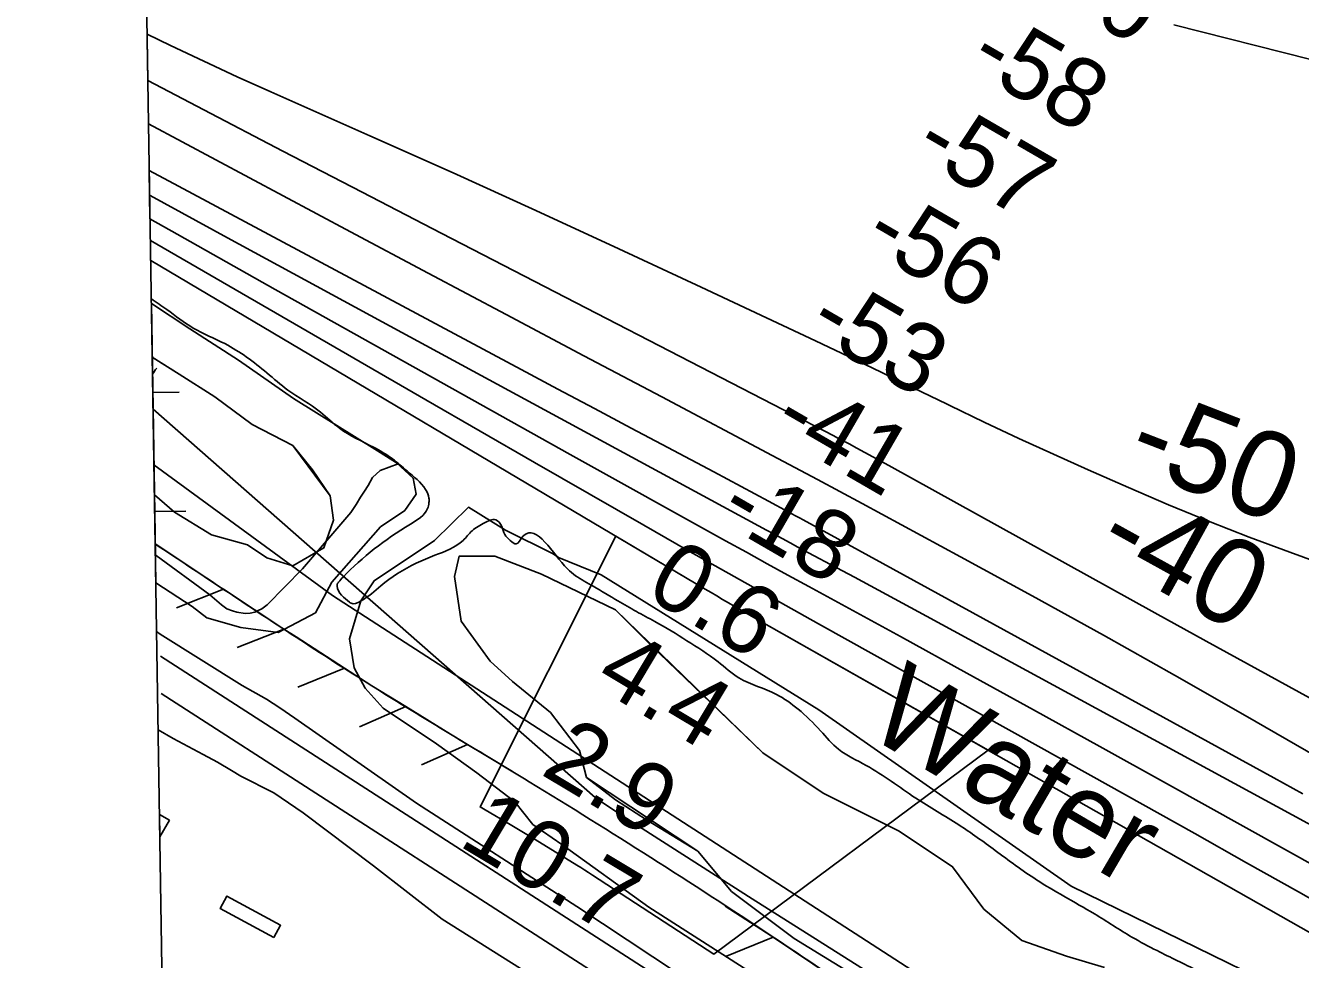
# Model space of a CAD drawing. Extents: x 3855477 to 3893699, y 299188 to 325115.
# Drawn here: x 3859445 to 3860680, y 314472 to 315377 of the extents above; entities that cross this region are included whole.
import ezdxf

# ---------------------------------------------------------------- set-up
doc = ezdxf.new("R2010")
doc.units = 0
for name, color, linetype in [('V-BLDG-OTLN', 7, 'Continuous'), ('V-GRID-FRAM', 7, 'Continuous'), ('V-LEVE-TOET', 7, 'Continuous'), ('V-RIVR-EDGE', 7, 'Continuous'), ('V-RIVR-IDEN', 7, 'Continuous'), ('V-RIVR-RANG', 7, 'Continuous'), ('V-RRAP-FSHR', 7, 'Continuous'), ('V-SITE-VEGE', 7, 'Continuous'), ('V-SURV-LINE', 7, 'Continuous'), ('V-TOPO-DPTH', 7, 'Continuous'), ('V-TOPO-MAJR', 7, 'Continuous'), ('V-TOPO-MAJR-IDEN', 7, 'Continuous'), ('V-TOPO-MINR', 7, 'Continuous'), ('V-TOPO-MINR-IDEN', 7, 'Continuous'), ('V-TOPO-SHOR', 7, 'Continuous'), ('V-TOPO-WATR', 7, 'Continuous'), ('V-WETL-SWMP', 7, 'Continuous')]:
    doc.layers.add(name, color=color, linetype=linetype)

msp = doc.modelspace()

# ---------------------------------------------------------------- linework, layer by layer
at = {"layer": 'V-BLDG-OTLN'}
for p, q in [((3859575.4, 314591.1), (3859575.1, 314612.7)), ((3859575.1, 314612.7), (3859584.7, 314607.2)), ((3859584.7, 314607.2), (3859575.4, 314591.1))]:
    msp.add_line(p, q, dxfattribs=at)
msp.add_lwpolyline([(3859685.8, 314493.4), (3859633.9, 314521.6), (3859640.4, 314533.6), (3859692.3, 314505.4)], close=True, dxfattribs=at)
at = {"layer": 'V-GRID-FRAM'}
msp.add_lwpolyline([(3859445.3, 322797), (3891292.6, 323315.8), (3891596.8, 305135.9), (3859733.6, 304616.8), (3859445.3, 322797)], dxfattribs=at)
at = {"layer": 'V-LEVE-TOET'}
for points in [[(3862242.2, 313100.5), (3862093.7, 313191.4), (3861941.9, 313285.1), (3861815.6, 313363.6), (3861686.6, 313438.4), (3861563.5, 313515.7), (3861444.2, 313584.7), (3861308.7, 313671.1), (3861176.5, 313754.8), (3861033.5, 313846.5), (3860865.7, 313952.6), (3860666.5, 314081.9), (3860455.2, 314218.1), (3860280.2, 314328.3), (3860126.5, 314425.9), (3859979.2, 314523.5), (3859824, 314623.6), (3859706.2, 314705.8), (3859691.7, 314716.1), (3859678.8, 314724.5), (3859655.1, 314737.6), (3859575.8, 314787.4), (3859572.3, 314789.8)], [(3859573.8, 314694.8), (3859588.3, 314686.4), (3859617.3, 314670.8), (3859631.3, 314663.3), (3859644.8, 314655.3), (3859654, 314649.7), (3859685.8, 314633.6), (3859714.4, 314614.3), (3859782.2, 314562.9), (3859848.9, 314511.4), (3859933.3, 314457.9), (3859995.9, 314420.4), (3860084.2, 314363.8), (3860165, 314312), (3860251.4, 314257.3), (3860353.4, 314191.6), (3860436.3, 314134.5), (3860515.4, 314085.3), (3860590.9, 314036.6), (3860660.7, 313988.8), (3860749.4, 313935.7)]]:
    msp.add_lwpolyline(points, dxfattribs=at)
at = {"layer": 'V-RIVR-EDGE'}
msp.add_spline([(3859567.2, 315112.1), (3859582.1, 315101.8), (3859607.8, 315083.8), (3859638.4, 315068.7), (3859679.1, 315040.4), (3859699.4, 315023.8), (3859731, 315002.4), (3859749.4, 314986.8), (3859782.4, 314968.3), (3859800.8, 314957.1), (3859814.8, 314945.4), (3859832.8, 314927.4), (3859836.1, 314919.1), (3859836.1, 314914.7), (3859834.7, 314908.9), (3859818.1, 314893.9), (3859752.9, 314842.6), (3859748.5, 314837.7), (3859747.1, 314835.3), (3859747.1, 314833.8), (3859759.2, 314818.3), (3859760.6, 314817.3), (3859769.8, 314819.2), (3859789.3, 314834.2), (3859823.8, 314856), (3859841.8, 314863.7), (3859869.1, 314878.2), (3859877.8, 314887.4), (3859890, 314895.2), (3859895.3, 314897.6), (3859900.7, 314898.1), (3859906.5, 314891.7), (3859909.4, 314883.9), (3859914.7, 314878.1), (3859920.5, 314874.7), (3859926.9, 314882), (3859927.8, 314882.9), (3859970, 314850.8), (3859986.5, 314838.6), (3859995.2, 314833.7), (3860019, 314819.6), (3860036.9, 314809.3), (3860054.9, 314799.6), (3860085.9, 314781), (3860116, 314760.6), (3860136.3, 314745), (3860172.7, 314728.9), (3860193.5, 314714.7), (3860215.3, 314693.8), (3860232.8, 314675.8), (3860259.5, 314660.2), (3860307.5, 314628.5), (3860349.2, 314602.6), (3860384.5, 314577.8), (3860424.3, 314549.5), (3860451, 314533.4), (3860480.5, 314516.4), (3860516.9, 314493.9), (3860541.2, 314480.8), (3860580.5, 314461.2), (3860606.2, 314447.1), (3860637.2, 314429.5), (3860661.4, 314415.4), (3860700.7, 314395.4), (3860743.4, 314370), (3860763.8, 314358.3), (3860794.3, 314340.3), (3860827.8, 314322.7), (3860852.5, 314307.6), (3860870.5, 314295.4), (3860907.3, 314274.4), (3860941.3, 314254), (3860954.8, 314253), (3860974.2, 314243.2), (3861007.7, 314223.7), (3861035.3, 314204.7), (3861088.7, 314172), (3861147.4, 314134.5), (3861171.6, 314117.4), (3861230.3, 314081.8)], degree=3, dxfattribs=at)
at = {"layer": 'V-RRAP-FSHR'}
for p, q in [((3859637.1, 314830.8), (3859591.7, 314812.9)), ((3859695.6, 314792.3), (3859650.3, 314774.3)), ((3859754.4, 314754.3), (3859709.2, 314735.9)), ((3859813.7, 314717.1), (3859768.9, 314697.6)), ((3859873.4, 314680.6), (3859828.7, 314660.9)), ((3860169.4, 314493.9), (3860124.2, 314475.4))]:
    msp.add_line(p, q, dxfattribs=at)
for points in [[(3859569.7, 314951.3), (3859742.7, 314824.8), (3861446, 313723)], [(3859637.1, 314830.8), (3859634.3, 314832.6), (3859602.6, 314853.7), (3859570.9, 314874.7)], [(3859578.8, 314869.5), (3859570.9, 314874.7)], [(3859695.6, 314792.3), (3859637.1, 314830.8)], [(3859754.4, 314754.3), (3859707.4, 314784.6), (3859695.6, 314792.3)], [(3859813.7, 314717.1), (3859780.9, 314737.2), (3859754.4, 314754.3)], [(3859873.4, 314680.6), (3859856.9, 314690.5), (3859813.7, 314717.1)], [(3859916.9, 314654.2), (3859873.4, 314680.6)], [(3860169.4, 314493.9), (3860167.5, 314495.2), (3860122.8, 314523.9)], [(3860227.5, 314454.8), (3860169.4, 314493.9)]]:
    msp.add_lwpolyline(points, dxfattribs=at)
msp.add_spline([(3860530.3, 314255.7), (3860362.1, 314364.4), (3860167.5, 314495.2), (3859933.2, 314644.3), (3859780.9, 314737.2), (3859634.3, 314832.6), (3859570.9, 314874.7)], degree=3, dxfattribs=at)
at = {"layer": 'V-SITE-VEGE'}
for p, q in [((3859568.1, 315055.7), (3859567.2, 315107.6)), ((3859567.2, 315107.6), (3859604.4, 315083)), ((3859604.4, 315083), (3859651.5, 315052.7)), ((3859569, 315055), (3859568.1, 315055.7)), ((3859594.2, 315039.2), (3859569, 315055)), ((3859651.5, 315052.7), (3859705, 315015.5)), ((3859628.8, 315017.2), (3859594.2, 315039.2)), ((3859665, 314990.5), (3859628.8, 315017.2)), ((3859705, 315015.5), (3859786.1, 314965)), ((3859704.3, 314970), (3859665, 314990.5)), ((3859723.2, 314946.4), (3859704.3, 314970)), ((3859786.1, 314965), (3859804.7, 314953.3)), ((3859740.5, 314921.2), (3859723.2, 314946.4)), ((3859804.7, 314953.3), (3859820.7, 314938.5)), ((3859820.7, 314938.5), (3859823.8, 314922.8)), ((3859571.5, 314837), (3859570.2, 314922.4)), ((3859570.2, 314922.4), (3859589.5, 314905.5)), ((3859743.6, 314897.6), (3859740.5, 314921.2)), ((3859823.8, 314922.8), (3859812.8, 314907.1)), ((3859589.5, 314905.5), (3859625.6, 314883.5)), ((3859734.2, 314870.9), (3859743.6, 314897.6)), ((3859812.8, 314907.1), (3859789.2, 314891.3)), ((3859625.6, 314883.5), (3859660.2, 314874)), ((3859789.2, 314891.3), (3859742, 314837.8)), ((3859660.2, 314874), (3859679.1, 314861.4)), ((3859704.3, 314853.6), (3859734.2, 314870.9)), ((3859679.1, 314861.4), (3859704.3, 314853.6)), ((3859606.8, 314814.2), (3859571.5, 314837)), ((3859742, 314837.8), (3859726.3, 314807.9)), ((3859620.9, 314803.2), (3859606.8, 314814.2)), ((3859654, 314793.8), (3859620.9, 314803.2)), ((3859726.3, 314807.9), (3859690.1, 314789)), ((3859690.1, 314789), (3859654, 314793.8))]:
    msp.add_line(p, q, dxfattribs=at)
for points in [[(3860972.6, 313934.4), (3860656.8, 314137.9), (3860373.5, 314315.3), (3860049, 314523), (3859964.7, 314583.6), (3859936.6, 314603.1), (3859919.2, 314624.8), (3859882.5, 314652.9), (3859843.5, 314681), (3859791.6, 314715.6), (3859774.3, 314735.1), (3859763.5, 314754.6), (3859759.2, 314782.7), (3859770, 314819.5), (3859783, 314839), (3859841.4, 314877.9), (3859874.3, 314910.3), (3859910.1, 314887.9), (3859956.4, 314865.2), (3859961.6, 314861.7), (3860002.9, 314844.7), (3860213.8, 314714.1)], [(3860490.3, 314464.6), (3860453.5, 314475.4), (3860410.2, 314490.6), (3860373.5, 314520.9), (3860343.2, 314562), (3860291.3, 314596.6), (3860217.7, 314633.4), (3860159.3, 314672.4), (3860100.9, 314728.6), (3860051.2, 314776.2), (3860016.6, 314810.9), (3859945.2, 314845.5), (3859899.8, 314862.8), (3859865.2, 314862.8), (3859860.8, 314843.3), (3859867.3, 314800), (3859895.5, 314761.1), (3859917.1, 314741.6), (3859953.9, 314711.3), (3859982, 314674.5), (3859988.5, 314648.6), (3860016.6, 314626.9), (3860046.9, 314607.4), (3860096.6, 314577.1), (3860129.1, 314538.2), (3860189.6, 314492.7), (3860256.7, 314451.6)], [(3860213.8, 314714.1), (3860458.1, 314543.3), (3860776.1, 314387.6)]]:
    msp.add_lwpolyline(points, dxfattribs=at)
at = {"layer": 'V-SURV-LINE'}
for points in [[(3859576.2, 314766.1), (3861236.1, 313696.1)], [(3861219.9, 313670.9), (3859576.8, 314730)]]:
    msp.add_lwpolyline(points, dxfattribs=at)
at = {"layer": 'V-TOPO-DPTH'}
for p, q in [((3859525.1, 317764.7), (3859563.8, 315323.6)), ((3859565.2, 315236.5), (3859565.9, 315189.6))]:
    msp.add_line(p, q, dxfattribs=at)
for points in [[(3859563.8, 315323.6), (3859618.2, 315295.1), (3859694.7, 315255.1), (3859771.4, 315215.3), (3859848, 315175.7), (3860219.6, 314983.8), (3860227.4, 314979.8), (3860235.1, 314975.7), (3860242.9, 314971.7), (3860250.6, 314967.6), (3860258.3, 314963.4), (3860266.1, 314959.2), (3860273.7, 314955), (3860281.4, 314950.8), (3860539, 314808.1), (3860588.8, 314780.6), (3860638.7, 314753.1), (3860688.7, 314725.8)], [(3859563.8, 315323.6), (3859618.2, 315295.1), (3859694.7, 315255.1), (3859771.4, 315215.3), (3859848, 315175.7), (3860219.6, 314983.8), (3860227.4, 314979.8), (3860235.1, 314975.7), (3860242.9, 314971.7), (3860250.6, 314967.6), (3860258.3, 314963.4), (3860266.1, 314959.2), (3860273.7, 314955), (3860281.4, 314950.8), (3860539, 314808.1), (3860588.8, 314780.6), (3860638.7, 314753.1), (3860688.7, 314725.8)], [(3860794, 314612), (3860626.5, 314708.5), (3860558, 314747.6), (3860489.3, 314786.3), (3860420.3, 314824.5), (3860351, 314862.3), (3860255.7, 314913.8), (3860234, 314925.5), (3860212.2, 314937.2), (3860190.4, 314948.8), (3860168.6, 314960.4), (3860061.5, 315017.1), (3859986.1, 315057), (3859910.7, 315097), (3859835.4, 315137.1), (3859760.1, 315177.1), (3859564.5, 315281.5)], [(3860794, 314612), (3860626.5, 314708.5), (3860558, 314747.6), (3860489.3, 314786.3), (3860420.3, 314824.5), (3860351, 314862.3), (3860255.7, 314913.8), (3860234, 314925.5), (3860212.2, 314937.2), (3860190.4, 314948.8), (3860168.6, 314960.4), (3860061.5, 315017.1), (3859986.1, 315057), (3859910.7, 315097), (3859835.4, 315137.1), (3859760.1, 315177.1), (3859564.5, 315281.5)], [(3860682.3, 314632.8), (3860654.2, 314648.3), (3860198.4, 314898), (3860194.8, 314900), (3860191.2, 314901.9), (3860187.6, 314903.9), (3860184, 314905.9), (3860164.8, 314916.2), (3860151.6, 314923.3), (3860138.4, 314930.4), (3860125.1, 314937.4), (3860111.9, 314944.5), (3860067.3, 314968.1), (3860031.8, 314986.9), (3859996.4, 315005.8), (3859960.9, 315024.7), (3859925.4, 315043.7), (3859593.5, 315221.4), (3859565.2, 315236.5)], [(3859565.2, 315236.5), (3859593.5, 315221.4), (3859925.4, 315043.7), (3859960.9, 315024.7), (3859996.4, 315005.8), (3860031.8, 314986.9), (3860067.3, 314968.1), (3860111.9, 314944.5), (3860125.1, 314937.4), (3860138.4, 314930.4), (3860151.6, 314923.3), (3860164.8, 314916.2), (3860184, 314905.9), (3860187.6, 314903.9), (3860191.2, 314901.9), (3860194.8, 314900), (3860198.4, 314898), (3860654.2, 314648.3), (3860682.3, 314632.8)], [(3859565.9, 315189.6), (3859592.1, 315174.9), (3859687.2, 315121.3), (3859782.3, 315067.9), (3859877.5, 315014.7), (3859972.8, 314961.5), (3860123.4, 314877.7), (3860143.5, 314866.6), (3860163.6, 314855.5), (3860183.7, 314844.5), (3860203.8, 314833.4), (3860292.6, 314784.9), (3860357.1, 314749.6), (3860421.5, 314714.1), (3860485.9, 314678.5), (3860550.2, 314642.8), (3860738.8, 314537.9)], [(3860738.8, 314537.9), (3860550.2, 314642.8), (3860485.9, 314678.5), (3860421.5, 314714.1), (3860357.1, 314749.6), (3860292.6, 314784.9), (3860203.8, 314833.4), (3860183.7, 314844.5), (3860163.6, 314855.5), (3860143.5, 314866.6), (3860123.4, 314877.7), (3859972.8, 314961.5), (3859877.5, 315014.7), (3859782.3, 315067.9), (3859687.2, 315121.3), (3859592.1, 315174.9), (3859565.9, 315189.6)], [(3859566.6, 315149.2), (3860103.7, 314830.9), (3860109.3, 314827.6), (3860114.9, 314824.3), (3860120.4, 314821), (3860126, 314817.7), (3860131.6, 314814.5), (3860137.2, 314811.2), (3860142.8, 314808), (3860148.4, 314804.8), (3860729, 314475.6)], [(3860017.2, 314882.1), (3859885.6, 314620), (3859890.5, 314617.3), (3859914.8, 314603), (3859939, 314588.5), (3859979.4, 314563.5), (3859983.2, 314561.2), (3859986.9, 314558.8), (3859990.7, 314556.4), (3859994.5, 314554), (3860112.1, 314477.4), (3860377.6, 314674.9)], [(3860377.6, 314674.9), (3860148.4, 314804.8), (3860142.8, 314808), (3860137.2, 314811.2), (3860131.6, 314814.5), (3860126, 314817.7), (3860120.4, 314821), (3860114.9, 314824.3), (3860109.3, 314827.6), (3860103.7, 314830.9), (3860017.2, 314882.1)]]:
    msp.add_lwpolyline(points, dxfattribs=at)
at = {"layer": 'V-TOPO-MAJR'}
msp.add_lwpolyline([(3859563.1, 315368.6), (3859585.6, 315357.6), (3859617.9, 315342.2), (3859650.4, 315327.3), (3859683, 315312.6), (3859778.9, 315270.1), (3859859.4, 315234.1), (3859939.7, 315197.7), (3860019.8, 315160.7), (3860099.8, 315123.4), (3860210.5, 315071.3), (3860242.3, 315056.2), (3860274, 315041), (3860305.7, 315025.7), (3860337.3, 315010.3), (3860340.5, 315008.8), (3860373.8, 314992.7), (3860407.2, 314977), (3860440.8, 314961.6), (3860474.5, 314946.5), (3860513.4, 314929.3), (3860552.2, 314912.7), (3860591.1, 314896.7), (3860630.3, 314881.4), (3860669.8, 314866.7), (3860709.4, 314852.3)], dxfattribs=at)
at = {"layer": 'V-TOPO-MINR'}
for points in [[(3860557.5, 315377.4), (3860690.2, 315344.1), (3860729.4, 315334.1), (3860768.6, 315323.9), (3860807.6, 315313.3), (3860846.6, 315302.5), (3860869.2, 315296.1), (3860896.8, 315288.1), (3860924.3, 315280.1), (3860951.7, 315271.7), (3860979.1, 315263.3), (3861006.4, 315254.6), (3861033.6, 315245.7), (3861060.8, 315236.7), (3861088, 315227.5), (3861163.2, 315201.9), (3861183.2, 315195.1), (3861203.2, 315188.4), (3861223.3, 315181.8), (3861243.4, 315175.3), (3861325.2, 315149), (3861336, 315146), (3862818.2, 314789)], [(3859563.8, 315323.6), (3859618.2, 315295.1), (3859694.7, 315255.1), (3859771.4, 315215.3), (3859848, 315175.7), (3860219.6, 314983.8), (3860227.4, 314979.8), (3860235.1, 314975.7), (3860242.9, 314971.7), (3860250.6, 314967.6), (3860258.3, 314963.4), (3860266.1, 314959.2), (3860273.7, 314955), (3860281.4, 314950.8), (3860539, 314808.1), (3860588.8, 314780.6), (3860638.7, 314753.1), (3860688.7, 314725.8)], [(3859564.5, 315281.5), (3859760.1, 315177.1), (3859835.4, 315137.1), (3859910.7, 315097), (3859986.1, 315057), (3860061.5, 315017.1), (3860168.6, 314960.4), (3860190.4, 314948.8), (3860212.2, 314937.2), (3860234, 314925.5), (3860255.7, 314913.8), (3860351, 314862.3), (3860420.3, 314824.5), (3860489.3, 314786.3), (3860558, 314747.6), (3860626.5, 314708.5), (3860794, 314612)], [(3859565.2, 315236.5), (3859593.5, 315221.4), (3859925.4, 315043.7), (3859960.9, 315024.7), (3859996.4, 315005.8), (3860031.8, 314986.9), (3860067.3, 314968.1), (3860111.9, 314944.5), (3860125.1, 314937.4), (3860138.4, 314930.4), (3860151.6, 314923.3), (3860164.8, 314916.2), (3860184, 314905.9), (3860187.6, 314903.9), (3860191.2, 314901.9), (3860194.8, 314900), (3860198.4, 314898), (3860654.2, 314648.3), (3860682.3, 314632.8)], [(3859565.6, 315212.5), (3859566.2, 315212.2), (3859640.9, 315171.2), (3859715.8, 315130.5), (3859790.6, 315089.8), (3860162.8, 314888.2), (3860170.5, 314884.1), (3860178.1, 314879.9), (3860185.8, 314875.8), (3860193.4, 314871.7), (3860224.8, 314854.9), (3860248.1, 314842.4), (3860271.4, 314829.9), (3860294.7, 314817.3), (3860317.9, 314804.7), (3860795.2, 314545.6)], [(3859565.9, 315189.6), (3859592.1, 315174.9), (3859687.2, 315121.3), (3859782.3, 315067.9), (3859877.5, 315014.7), (3859972.8, 314961.5), (3860123.4, 314877.7), (3860143.5, 314866.6), (3860163.6, 314855.5), (3860183.7, 314844.5), (3860203.8, 314833.4), (3860292.6, 314784.9), (3860357.1, 314749.6), (3860421.5, 314714.1), (3860485.9, 314678.5), (3860550.2, 314642.8), (3860738.8, 314537.9)], [(3859566.3, 315168.6), (3859832.9, 315014.3), (3859885.6, 314983.9), (3859938.4, 314953.5), (3859991.3, 314923.2), (3860044.1, 314893), (3860086.9, 314868.5), (3860118.4, 314850.6), (3860150, 314832.7), (3860181.6, 314815), (3860213.3, 314797.3), (3860477.1, 314650.3), (3860527.4, 314622.3), (3860577.7, 314594.1), (3860627.9, 314565.9), (3860678.1, 314537.7), (3860749.8, 314497.1), (3860764.1, 314489), (3860778.3, 314480.9), (3860792.5, 314472.7), (3860806.6, 314464.5), (3861580.1, 313986), (3862193.6, 313608.9)], [(3859568.9, 315005.4), (3859997.1, 314629), (3860008.4, 314621.4), (3860019.7, 314613.9), (3860031.1, 314606.4), (3860042.6, 314599), (3860149.1, 314531.1), (3860213.9, 314490), (3860278.9, 314449.1), (3860344, 314408.4), (3860409.3, 314368), (3860580.6, 314262.5), (3860604.9, 314247.6), (3860629.2, 314232.7), (3860653.5, 314217.9), (3860677.8, 314203), (3861055.2, 313973.3)], [(3859885.6, 314620), (3859890.5, 314617.3), (3859914.8, 314603), (3859939, 314588.5), (3859979.4, 314563.5), (3859983.2, 314561.2), (3859986.9, 314558.8), (3859990.7, 314556.4), (3859994.5, 314554), (3860112.1, 314477.4)]]:
    msp.add_lwpolyline(points, dxfattribs=at)
at = {"layer": 'V-TOPO-SHOR'}
for points in [[(3859568.1, 315055.7), (3859594.2, 315039.2), (3859628.8, 315017.2), (3859665, 314990.5), (3859704.3, 314970), (3859740.5, 314921.2), (3859743.6, 314897.6), (3859734.2, 314870.9), (3859704.3, 314853.6), (3859679.1, 314861.4), (3859660.2, 314874), (3859625.6, 314883.5), (3859589.5, 314905.5), (3859570.2, 314922.4)], [(3860490.3, 314464.6), (3860453.5, 314475.4), (3860410.2, 314490.6), (3860373.5, 314520.9), (3860343.2, 314562), (3860291.3, 314596.6), (3860217.7, 314633.4), (3860159.3, 314672.4), (3860016.6, 314810.9), (3859945.2, 314845.5), (3859899.8, 314862.8), (3859865.2, 314862.8), (3859860.8, 314843.3), (3859867.3, 314800), (3859895.5, 314761.1), (3859917.1, 314741.6), (3859953.9, 314711.3), (3859982, 314674.5), (3859988.5, 314648.6), (3860096.6, 314577.1), (3860129.1, 314538.2), (3860189.6, 314492.7), (3860256.7, 314451.6)]]:
    msp.add_lwpolyline(points, dxfattribs=at)
at = {"layer": 'V-TOPO-WATR'}
msp.add_lwpolyline([(3859566.6, 315149.2), (3860103.7, 314830.9), (3860109.3, 314827.6), (3860114.9, 314824.3), (3860120.4, 314821), (3860126, 314817.7), (3860131.6, 314814.5), (3860137.2, 314811.2), (3860142.8, 314808), (3860148.4, 314804.8), (3860729, 314475.6)], dxfattribs=at)
at = {"layer": 'V-WETL-SWMP'}
for p, q in [((3859571.1, 314864.1), (3859567.2, 315107.6)), ((3859567.2, 315107.6), (3859604.4, 315083)), ((3859604.4, 315083), (3859651.5, 315052.7)), ((3859651.5, 315052.7), (3859705, 315015.5)), ((3859568.6, 315021.4), (3859594.2, 315021.8)), ((3859705, 315015.5), (3859786.1, 314965)), ((3859786.1, 314965), (3859806.3, 314952.3)), ((3859788.9, 314945.9), (3859781.4, 314939.1)), ((3859806.3, 314952.3), (3859788.9, 314945.9)), ((3859781.4, 314939.1), (3859777.3, 314931.3)), ((3859773.6, 314925.7), (3859769.9, 314920)), ((3859777.3, 314931.3), (3859773.6, 314925.7)), ((3859765.6, 314913), (3859760.3, 314905.3)), ((3859769.9, 314920), (3859765.6, 314913)), ((3859570.4, 314906), (3859600.6, 314906.5)), ((3859760.3, 314905.3), (3859713.5, 314850.6)), ((3859572, 314863.5), (3859571.1, 314864.1)), ((3859623.8, 314825.4), (3859572, 314863.5)), ((3859713.5, 314850.6), (3859679.5, 314815.6)), ((3859635.2, 314815.7), (3859623.8, 314825.4)), ((3859640.3, 314812), (3859635.2, 314815.7)), ((3859645.7, 314809.8), (3859640.3, 314812)), ((3859650.1, 314808.6), (3859645.7, 314809.8)), ((3859670.5, 314810.1), (3859667.4, 314808.6)), ((3859674.1, 314812), (3859670.5, 314810.1)), ((3859679.5, 314815.6), (3859674.1, 314812)), ((3859658, 314807.2), (3859650.1, 314808.6)), ((3859662.8, 314807.5), (3859658, 314807.2)), ((3859667.4, 314808.6), (3859662.8, 314807.5))]:
    msp.add_line(p, q, dxfattribs=at)
msp.add_arc((3859599.4, 315022.4), 35.2, 140.1615, 151.8293, dxfattribs=at)

# ---------------------------------------------------------------- texts
at = {"layer": 'V-RIVR-IDEN'}
msp.add_text('Water ', height=83, rotation=329.6492, dxfattribs=at).set_placement((3860256.7, 314691.3))
at = {"layer": 'V-RIVR-RANG'}
for s, rotation, p in [('-60', 329.9134, (3860408.6, 315421.1)), ('-58', 329.9134, (3860355.9, 315336.1)), ('-57', 329.9134, (3860302.9, 315251.3)), ('-56', 329.9134, (3860254, 315164)), ('-53', 329.9134, (3860200.1, 315079.7)), ('-41', 329.9134, (3860165.7, 314984.1)), ('-18', 329.9134, (3860113.8, 314898.5)), ('0.6', 329.0983, (3860043.7, 314825)), ('4.4', 329.0983, (3859994.2, 314738.2)), ('2.9', 329.0983, (3859942.8, 314652.4)), ('10.7', 329.0983, (3859863.3, 314583.4))]:
    msp.add_text(s, height=67, rotation=rotation, dxfattribs=at).set_placement(p)
at = {"layer": 'V-TOPO-MAJR-IDEN'}
msp.add_text('-50', height=83, rotation=338.7847, dxfattribs=at).set_placement((3860508.4, 314951))
at = {"layer": 'V-TOPO-MINR-IDEN'}
msp.add_text('-40', height=83, rotation=331.0821, dxfattribs=at).set_placement((3860478.5, 314865.2))

doc.saveas('drawing.dxf')
